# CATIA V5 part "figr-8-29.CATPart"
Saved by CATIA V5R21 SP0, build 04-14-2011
Part number: Part1
Bounding box of the stored display mesh (mm): x 37.5 to 207.5, y 10 to 85, z 0 to 113
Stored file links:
  D:\CATIA V5R21 E-RESOURCES\CATIA-V5R21\catia-v5r21-prt\c08-catia-v5r20-prt\c08-catia-v5r21-figr-8-29.CATPart
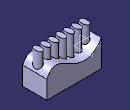
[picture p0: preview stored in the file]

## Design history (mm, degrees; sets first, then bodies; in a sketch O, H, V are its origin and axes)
Set1
  Plane1: type Offset, RefPlane xy-plane, Offset 113
Body1 (main body)
  Sketch1 on xy-plane, origin (0, 0, 0), H (1, 0, 0), V (0, 1, 0)
    line L1 (-37.5, 85) -> (37.5, 85)
    line L2 (37.5, 85) -> (37.5, -85)
    line L3 (37.5, -85) -> (-37.5, -85)
    line L4 (-37.5, -85) -> (-37.5, 85)
    axis line L5 (37.5, -85) -> (-37.5, 85)
    length L3 = 75
    length L2 = 170
    horizontal: L1 H, L3 H
    vertical: L2 V, L4 V
    midpoint: O L5
  Pad1: profile Sketch1, direction (0, 0, 1), length 83
  Sketch2 on face of Pad1, origin (37.5, 0, 0), H (0, 1, 0), V (0, 0, 1)
    spline S1 through (-85, 56.7422) (-58.5369, 80.0687) (-27.7952, 70.201) (85, 83)
    reference projected line E1 (85, 0) -> (85, 83) from edge [face of Pad1 | face of Pad1]
    reference projected line E2 (-85, 0) -> (-85, 83) from edge [face of Pad1 | face of Pad1]
    reference projected line E3 (-85, 83) -> (85, 83) from edge [face of Pad1 | face of Pad1]
    point P1 (85, 83)
    point P3 (-85, 56.7422)
    coincidence: P1 E1, P3 E2, P1 E3
  Pocket1: profile Sketch2, direction (-1, 0, 0), length 83
  Rotate1: Axis edge [face of Pad1 | face of Pad1], Angle 90, ToTransfor Pocket1
  Sketch3 on Plane1, origin (0, 0, 113), H (1, 0, 0), V (0, 1, 0)
    ellipse A1 centre (195.4286, 45.9861) semi-axes 14.9247, 8.8005 rotation 90
  Pad2: profile Sketch3, direction (0, 0, -1), up to face of Pocket1
  RectPattern1: of Pad2, direction 1 instances 7, spacing 24, along edge [face of Pad1 | face of Pad1]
